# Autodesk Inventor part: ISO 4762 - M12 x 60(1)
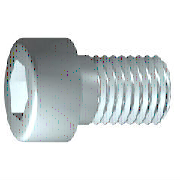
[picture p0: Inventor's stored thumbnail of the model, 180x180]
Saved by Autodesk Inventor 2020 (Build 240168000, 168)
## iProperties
Created: 2019-01
Part Number: ISO 4762 - M12 x 60(1)
Material: Nerezová ocel 440C
Description: Šroub s válcovou hlavou s vnitřním šestihranem
Document SubType Name: Modeling
Standard: ISO 4762
Designer: doma
Standard Revision: Fourth edition 2004-03-01
Standards Organization: ISO
Language: cs-CZ
Size Designation: M12 x 60
Categories: <MemberInstance><Categories><Category DisplayName="Spojovací materiál" InternalName="e4da775c-781d-43d5-af7c-5136215cf5a6" Mnemonic="FSTN"><Category DisplayName
Density: 7.75 g/cm^3
Appearance: Pololeštěná
IsCustomPart: 0
Author: doma
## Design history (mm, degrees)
sketch "Náčrt1"
  geometry: L1 (-2.667, 0)-(60, 0); L2 (60, 0)-(60, 6); L3 (60, 6)-(24, 6); L4 (24, 6)-(22.926, 6); L5 (22.926, 6)-(0, 6); L6 (0, 6)-(0, 9); L7 (0, 9)-(-12, 9); L8 (-12, 9)-(-12, 5.774); L9 (-12, 5.774)-(-6, 5.774); L10 (-6, 5.774)-(-2.667, 0); L11 (-26.4, 0)-(74.4, 0) reference; L12 (0, -1.8)-(0, 10.8) reference; L13 (24, 6)-(0, 6)
  constraints: 22 end point, 6 parallel, 2 collinear, 2 perpendicular, 1 horizontal, 1 point on line
  dimensions: "d1" = 36 distance from line of L3.end L2 (= GEL); "d2" = 1.07364 distance of L4.end L3.end (computed from GAL); "d3" = 12 distance between parallel lines of L8 L6 (= KOH); "d4" = 6 distance of L8.end L9.end (= INTI); "d5" = 60 deg angle of L10 L1; "d6" = 12 diameter of L3 L1 (= GD); "d7" = 12 diameter of L5 L1 (= BDM); "d8" = 11.54701 diameter of L9 L1 (= 1.1547 x SW); "d9" = 18 diameter of L7 L1 (= KOD); "d26" = 60 distance between parallel lines of L12 L2 (= NLG)
revolve "Těleso" sketch "Náčrt1" stored, may be unused: angle "d10" = 90 deg
sketch "Náčrt2"
  geometry: L1 (0, -12.6)-(0, 12.6) reference; L2 (-12.6, 0)-(12.6, 0) reference; L3 (5.774, 0)-(2.887, -5); L4 (2.887, -5)-(-2.887, -5); L5 (-2.887, -5)-(-5.774, 0); L6 (-5.774, 0)-(-2.887, 5); L7 (-2.887, 5)-(2.887, 5); L8 (2.887, 5)-(5.774, 0); 2 further points
  constraints: 12 end point, 1 coincident, 1 horizontal alignment, 1 point on line, 12 other
extrude "Drážka" join sketch "Náčrt2" stored distance "d11" = 10; taper "d12" = 0 deg
workplane "Work Plane1"
fillet "Fillet2" dims "d30" = 0.1 (= R)
body "Solid1"
fillet "Zaoblení1" dims "d17" = 1.2 (= RR)
feature "Závit" dims "d13" = 36 (= GEL), "d14" = 0
chamfer "Zkosení1" distance "d15" = 1.07354 (= -0.5 x SPD + 0.5 x GD); stored, may be unused: second distance "d16" = 1.07354 (= GUL), angle "d27" = 45 deg
other parameters: "GD" = 12 [user parameter; used in 2 equation terms], "NLG" = 60 [user parameter; used in 1 equation term], "GEL" = 36 [user parameter; used in 2 equation terms], "KOD" = 18 [user parameter; used in 1 equation term], "KOH" = 12 [user parameter; used in 1 equation term], "INTI" = 6 [user parameter; used in 1 equation term], "GAL" = 1.07354 (= 0.61345 x PTC) [user parameter; used in 1 equation term], "GUL" = 1.07354 (= 0.61345 x PTC) [user parameter; used in 1 equation term], "BDM" = 12 (= NND) [user parameter; used in 1 equation term], "RR" = 1.2 [user parameter; used in 1 equation term], "SPD" = 9.85293 (= NND - 1.2269 x PTC) [user parameter; used in 1 equation term], "d19" = 0, "d28" = 0, "d29" = 0, "R" = 0.1 [user parameter; used in 1 equation term], "TOA" = 30 deg [user parameter], "GD1" = 9.85293 (= THREADDIA - 1.2269 x PTC) [user parameter], "THREADDIA" = 12 [user parameter; used in 1 equation term], "FAWI" = 45 deg [user parameter], "TPU" = 5.71429 (computed from PTC) [user parameter], "PTC" = 1.75 [user parameter; used in 5 equation terms], "NND" = 12 [user parameter; used in 2 equation terms], "E0" = 11.55 (= 1.155 x SW) [user parameter]
